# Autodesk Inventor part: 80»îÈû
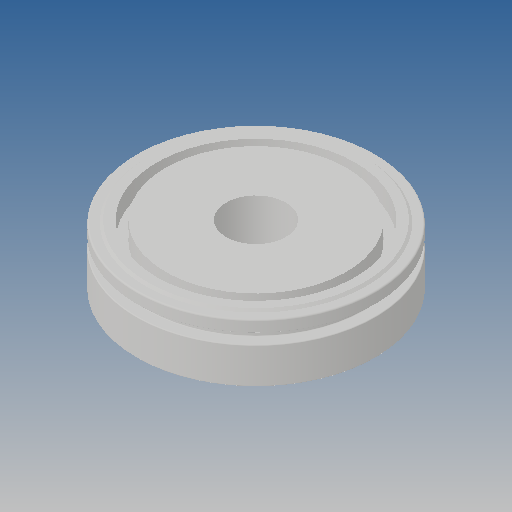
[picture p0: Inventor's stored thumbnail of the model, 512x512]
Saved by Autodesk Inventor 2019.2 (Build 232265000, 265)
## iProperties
Created: 2013-07
Part Number: 80»îÈû
Material: Ogólny
Document SubType Name: Modeling
Designer: CADENGINEERING4
Density: 1 g/cm^3
Appearance: Domyślna
Author: CADENGINEERING4
Revision Number: ÈÎºÎ
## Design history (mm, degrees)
feature "Ðý×ª1"
node "Bryła1"
